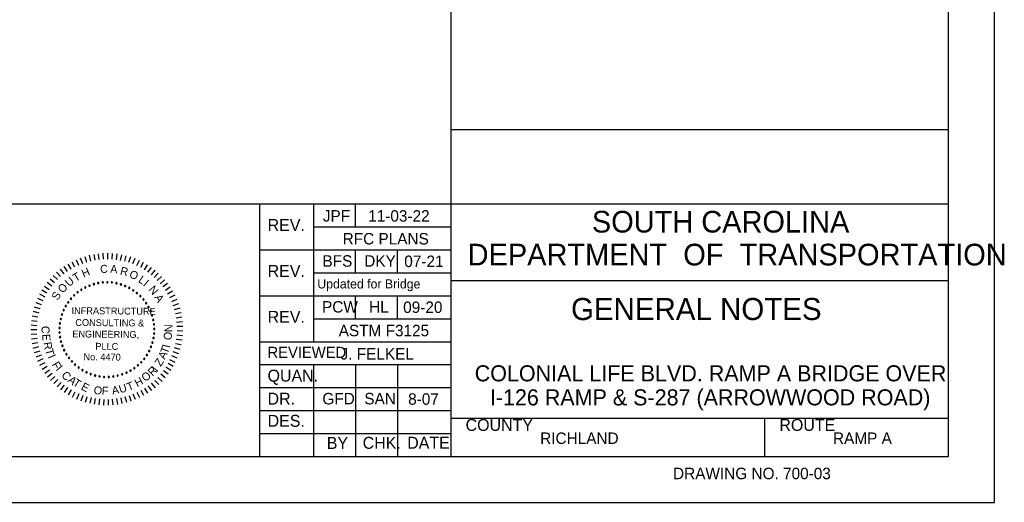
# Model space of a CAD drawing. Extents: x -1.3 to 34.8, y 0.8 to 22.8.
# Drawn here: x 24.06 to 34.78, y 0.82 to 6.08 of the extents above; entities that cross this region are included whole.
import ezdxf

# ---------------------------------------------------------------- set-up
doc = ezdxf.new("R2010")
doc.units = 0
for name, color, linetype in [('BR_BORDER LINES', 7, 'Continuous'), ('BR_TEXT', 7, 'Continuous'), ('Level 31', 7, 'Continuous')]:
    doc.layers.add(name, color=color, linetype=linetype)

msp = doc.modelspace()

# ---------------------------------------------------------------- linework, layer by layer
at = {"layer": 'BR_BORDER LINES'}
for p, q in [((34.177, 1.318), (34.177, 22.318)), ((28.76, 1.318), (28.76, 6.595)), ((28.76, 4.88), (34.177, 4.88)), ((21.311, 4.068), (26.676, 4.068)), ((26.676, 1.318), (26.676, 4.068)), ((26.676, 4.068), (34.177, 4.068)), ((27.26, 4.068), (27.26, 2.568)), ((27.718, 3.818), (27.718, 4.068)), ((27.26, 3.818), (28.76, 3.818)), ((26.676, 3.568), (28.76, 3.568)), ((27.718, 3.318), (27.718, 3.568)), ((28.176, 3.318), (28.176, 3.568)), ((27.26, 3.318), (28.76, 3.318)), ((28.76, 3.235), (28.76, 3.235)), ((28.76, 3.235), (34.177, 3.235)), ((26.676, 3.068), (28.76, 3.068)), ((27.718, 2.818), (27.718, 3.068)), ((28.176, 2.818), (28.176, 3.068)), ((27.26, 2.818), (28.76, 2.818)), ((26.676, 2.568), (28.76, 2.568)), ((26.676, 2.318), (28.76, 2.318)), ((27.26, 2.318), (27.26, 1.318)), ((27.718, 2.318), (27.718, 1.318)), ((28.176, 2.318), (28.176, 1.318)), ((26.676, 2.068), (28.76, 2.068)), ((26.676, 1.818), (28.76, 1.818)), ((28.76, 1.735), (34.177, 1.735)), ((28.857, 1.735), (34.177, 1.735)), ((32.177, 1.318), (32.177, 1.735)), ((26.676, 1.568), (28.76, 1.568)), ((0.511, 1.318), (34.177, 1.318))]:
    msp.add_line(p, q, dxfattribs=at)
at = {"layer": 'BR_TEXT'}
for p, q in [((24.629, 3.439), (24.658, 3.382)), ((24.674, 3.461), (24.7, 3.402)), ((24.721, 3.48), (24.743, 3.42)), ((24.769, 3.496), (24.788, 3.435)), ((24.818, 3.509), (24.832, 3.447)), ((24.867, 3.519), (24.878, 3.456)), ((24.917, 3.526), (24.924, 3.463)), ((24.967, 3.531), (24.971, 3.467)), ((25.018, 3.532), (25.017, 3.468)), ((25.068, 3.53), (25.064, 3.466)), ((25.118, 3.524), (25.11, 3.461)), ((25.168, 3.516), (25.156, 3.454)), ((25.218, 3.505), (25.202, 3.444)), ((25.266, 3.491), (25.246, 3.43)), ((25.313, 3.474), (25.29, 3.415)), ((25.36, 3.454), (25.333, 3.396)), ((24.463, 3.325), (24.505, 3.277)), ((24.501, 3.357), (24.541, 3.307)), ((24.542, 3.387), (24.578, 3.334)), ((24.585, 3.414), (24.618, 3.359)), ((25.405, 3.431), (25.375, 3.375)), ((25.449, 3.406), (25.415, 3.352)), ((25.491, 3.378), (25.454, 3.326)), ((25.531, 3.347), (25.491, 3.298)), ((24.391, 3.254), (24.439, 3.211)), ((24.426, 3.29), (24.471, 3.245)), ((25.569, 3.314), (25.526, 3.267)), ((25.605, 3.279), (25.559, 3.235)), ((25.639, 3.242), (25.591, 3.2)), ((24.301, 3.132), (24.356, 3.099)), ((24.329, 3.174), (24.381, 3.138)), ((24.359, 3.215), (24.409, 3.176)), ((25.671, 3.202), (25.62, 3.164)), ((25.7, 3.161), (25.647, 3.126)), ((25.726, 3.118), (25.671, 3.086)), ((24.255, 3.042), (24.313, 3.016)), ((24.277, 3.088), (24.333, 3.058)), ((25.75, 3.074), (25.693, 3.045)), ((25.772, 3.028), (25.713, 3.003)), ((24.206, 2.899), (24.268, 2.884)), ((24.219, 2.948), (24.28, 2.929)), ((24.235, 2.996), (24.295, 2.973)), ((25.79, 2.981), (25.73, 2.96)), ((25.805, 2.933), (25.744, 2.915)), ((24.188, 2.8), (24.251, 2.793)), ((24.195, 2.85), (24.258, 2.839)), ((25.818, 2.884), (25.756, 2.87)), ((25.827, 2.834), (25.764, 2.824)), ((24.182, 2.699), (24.246, 2.7)), ((24.184, 2.75), (24.247, 2.746)), ((25.834, 2.784), (25.77, 2.778)), ((25.837, 2.734), (25.773, 2.732)), ((25.837, 2.683), (25.774, 2.685)), ((24.184, 2.649), (24.248, 2.653)), ((24.189, 2.598), (24.252, 2.607)), ((25.829, 2.583), (25.766, 2.592)), ((25.835, 2.633), (25.771, 2.638)), ((24.197, 2.549), (24.259, 2.561)), ((24.208, 2.499), (24.27, 2.515)), ((24.222, 2.451), (24.282, 2.47)), ((25.808, 2.484), (25.747, 2.501)), ((25.82, 2.533), (25.758, 2.546)), ((24.239, 2.403), (24.298, 2.426)), ((24.259, 2.357), (24.316, 2.384)), ((25.755, 2.343), (25.697, 2.37)), ((25.775, 2.389), (25.716, 2.413)), ((25.793, 2.436), (25.733, 2.456)), ((24.281, 2.312), (24.337, 2.342)), ((24.306, 2.268), (24.36, 2.302)), ((24.334, 2.226), (24.386, 2.263)), ((25.705, 2.255), (25.652, 2.289)), ((25.731, 2.298), (25.676, 2.329)), ((24.365, 2.186), (24.414, 2.225)), ((24.397, 2.147), (24.445, 2.19)), ((24.433, 2.111), (24.477, 2.157)), ((25.576, 2.1), (25.532, 2.146)), ((25.612, 2.136), (25.565, 2.179)), ((25.645, 2.173), (25.596, 2.214)), ((25.676, 2.213), (25.625, 2.251)), ((24.47, 2.077), (24.511, 2.125)), ((24.509, 2.045), (24.548, 2.096)), ((24.55, 2.016), (24.585, 2.069)), ((24.593, 1.989), (24.625, 2.044)), ((25.457, 2.007), (25.422, 2.061)), ((25.498, 2.036), (25.461, 2.087)), ((25.538, 2.067), (25.497, 2.116)), ((24.637, 1.965), (24.666, 2.022)), ((24.683, 1.943), (24.708, 2.002)), ((24.73, 1.925), (24.751, 1.985)), ((24.778, 1.909), (24.796, 1.971)), ((24.827, 1.897), (24.841, 1.959)), ((24.876, 1.887), (24.887, 1.95)), ((24.927, 1.88), (24.933, 1.944)), ((24.977, 1.877), (24.979, 1.94)), ((25.027, 1.876), (25.026, 1.94)), ((25.078, 1.879), (25.072, 1.942)), ((25.128, 1.885), (25.119, 1.948)), ((25.178, 1.893), (25.165, 1.956)), ((25.227, 1.905), (25.21, 1.967)), ((25.275, 1.92), (25.255, 1.98)), ((25.322, 1.937), (25.298, 1.996)), ((25.369, 1.958), (25.341, 2.015)), ((25.413, 1.981), (25.382, 2.037))]:
    msp.add_line(p, q, dxfattribs=at)
for centre, start, end in [((24.966, 3.214), 5.0653, 185.0653), ((25.015, 3.215), 359.5268, 179.5268), ((25.065, 3.213), 353.9884, 173.9884), ((24.691, 3.105), 38.2961, 218.2961), ((24.732, 3.134), 32.7576, 212.7576), ((24.732, 3.134), 212.7576, 32.7576), ((24.775, 3.159), 27.2191, 207.2191), ((24.775, 3.159), 207.2191, 27.2191), ((24.821, 3.179), 21.6807, 201.6807), ((24.821, 3.179), 201.6807, 21.6807), ((24.868, 3.195), 16.1422, 196.1422), ((24.868, 3.195), 196.1422, 16.1422), ((24.916, 3.207), 10.6038, 190.6038), ((24.916, 3.207), 190.6038, 10.6038), ((24.966, 3.214), 185.0653, 5.0653), ((25.015, 3.215), 179.5268, 359.5268), ((25.065, 3.213), 173.9884, 353.9884), ((25.114, 3.205), 348.4499, 168.4499), ((25.114, 3.205), 168.4499, 348.4499), ((25.163, 3.192), 342.9114, 162.9114), ((25.163, 3.192), 162.9114, 342.9114), ((25.209, 3.175), 157.373, 337.373), ((25.209, 3.175), 337.373, 157.373), ((25.254, 3.154), 151.8345, 331.8345), ((25.254, 3.154), 331.8345, 151.8345), ((25.297, 3.128), 146.2961, 326.2961), ((25.297, 3.128), 326.2961, 146.2961), ((24.589, 2.997), 54.9114, 234.9114), ((24.589, 2.997), 234.9114, 54.9114), ((24.619, 3.036), 49.373, 229.373), ((24.619, 3.036), 229.373, 49.373), ((24.654, 3.072), 43.8345, 223.8345), ((24.654, 3.072), 223.8345, 43.8345), ((24.691, 3.105), 218.2961, 38.2961), ((25.337, 3.099), 140.7576, 320.7576), ((25.337, 3.099), 320.7576, 140.7576), ((25.374, 3.065), 135.2191, 315.2191), ((25.374, 3.065), 315.2191, 135.2191), ((25.408, 3.028), 129.6807, 309.6807), ((25.408, 3.028), 309.6807, 129.6807), ((24.539, 2.911), 65.9884, 245.9884), ((24.539, 2.911), 245.9884, 65.9884), ((24.562, 2.955), 60.4499, 240.4499), ((24.562, 2.955), 240.4499, 60.4499), ((25.437, 2.988), 124.1422, 304.1422), ((25.437, 2.988), 304.1422, 124.1422), ((25.463, 2.946), 118.6038, 298.6038), ((25.463, 2.946), 298.6038, 118.6038), ((25.485, 2.901), 113.0653, 293.0653), ((25.485, 2.901), 293.0653, 113.0653), ((24.508, 2.816), 77.0653, 257.0653), ((24.508, 2.816), 257.0653, 77.0653), ((24.521, 2.864), 71.5268, 251.5268), ((24.521, 2.864), 251.5268, 71.5268), ((25.502, 2.854), 107.5268, 287.5268), ((25.502, 2.854), 287.5268, 107.5268), ((25.515, 2.806), 101.9884, 281.9884), ((25.515, 2.806), 281.9884, 101.9884), ((24.495, 2.718), 88.1422, 268.1422), ((24.499, 2.767), 82.6038, 262.6038), ((24.495, 2.718), 268.1422, 88.1422), ((24.499, 2.767), 262.6038, 82.6038), ((25.523, 2.757), 96.4499, 276.4499), ((25.526, 2.707), 90.9114, 270.9114), ((25.523, 2.757), 276.4499, 96.4499), ((25.526, 2.707), 270.9114, 90.9114), ((24.495, 2.668), 93.6807, 273.6807), ((24.501, 2.618), 99.2191, 279.2191), ((24.495, 2.668), 273.6807, 93.6807), ((24.501, 2.618), 279.2191, 99.2191), ((24.511, 2.569), 104.7576, 284.7576), ((24.511, 2.569), 284.7576, 104.7576), ((25.518, 2.608), 79.8345, 259.8345), ((25.518, 2.608), 259.8345, 79.8345), ((25.524, 2.657), 85.373, 265.373), ((25.524, 2.657), 265.373, 85.373), ((24.526, 2.522), 110.2961, 290.2961), ((24.526, 2.522), 290.2961, 110.2961), ((24.545, 2.476), 115.8345, 295.8345), ((24.545, 2.476), 295.8345, 115.8345), ((25.47, 2.466), 63.2191, 243.2191), ((25.47, 2.466), 243.2191, 63.2191), ((25.49, 2.512), 68.7576, 248.7576), ((25.49, 2.512), 248.7576, 68.7576), ((25.506, 2.559), 74.2961, 254.2961), ((25.506, 2.559), 254.2961, 74.2961), ((24.569, 2.432), 121.373, 301.373), ((24.569, 2.432), 301.373, 121.373), ((24.597, 2.391), 126.9114, 306.9114), ((24.597, 2.391), 306.9114, 126.9114), ((24.629, 2.352), 312.4499, 132.4499), ((25.417, 2.382), 52.1422, 232.1422), ((25.417, 2.382), 232.1422, 52.1422), ((25.445, 2.423), 57.6807, 237.6807), ((25.445, 2.423), 237.6807, 57.6807), ((24.629, 2.352), 132.4499, 312.4499), ((24.664, 2.317), 137.9884, 317.9884), ((24.664, 2.317), 317.9884, 137.9884), ((24.703, 2.286), 143.5268, 323.5268), ((24.703, 2.286), 323.5268, 143.5268), ((24.744, 2.258), 149.0653, 329.0653), ((24.744, 2.258), 329.0653, 149.0653), ((25.267, 2.253), 29.9884, 209.9884), ((25.267, 2.253), 209.9884, 29.9884), ((25.309, 2.279), 35.5268, 215.5268), ((25.309, 2.279), 215.5268, 35.5268), ((25.348, 2.31), 41.0653, 221.0653), ((25.348, 2.31), 221.0653, 41.0653), ((25.384, 2.345), 46.6038, 226.6038), ((25.384, 2.345), 226.6038, 46.6038), ((24.788, 2.234), 154.6038, 334.6038), ((24.788, 2.234), 334.6038, 154.6038), ((24.834, 2.215), 340.1422, 160.1422), ((24.834, 2.215), 160.1422, 340.1422), ((24.882, 2.2), 345.6807, 165.6807), ((24.882, 2.2), 165.6807, 345.6807), ((24.93, 2.19), 351.2191, 171.2191), ((24.93, 2.19), 171.2191, 351.2191), ((24.98, 2.185), 356.7576, 176.7576), ((24.98, 2.185), 176.7576, 356.7576), ((25.03, 2.184), 2.2961, 182.2961), ((25.03, 2.184), 182.2961, 2.2961), ((25.079, 2.189), 7.8345, 187.8345), ((25.079, 2.189), 187.8345, 7.8345), ((25.128, 2.198), 13.373, 193.373), ((25.128, 2.198), 193.373, 13.373), ((25.176, 2.212), 18.9114, 198.9114), ((25.176, 2.212), 198.9114, 18.9114), ((25.223, 2.23), 24.4499, 204.4499), ((25.223, 2.23), 204.4499, 24.4499)]:
    msp.add_arc(centre, 0.00701, start, end, dxfattribs=at)
at = {"layer": 'Level 31'}
msp.add_line((31.468, 2.795), (31.468, 2.795), dxfattribs=at)
msp.add_lwpolyline([(-1.323, 22.818), (-1.323, 0.818), (34.677, 0.818), (34.677, 22.818)], dxfattribs=at)

# ---------------------------------------------------------------- texts
at = {"layer": 'BR_TEXT'}
for s, height, p in [('JPF', 0.125, (27.362, 3.876)), ('11-03-22', 0.125, (27.856, 3.876)), ('SOUTH CAROLINA', 0.23587, (30.292, 3.757)), ('REV.', 0.13, (26.761, 3.774)), ('RFC PLANS', 0.125, (27.578, 3.627)), ('DEPARTMENT  OF  TRANSPORTATION', 0.23587, (28.939, 3.399)), ('BFS', 0.125, (27.358, 3.385)), ('DKY', 0.125, (27.813, 3.385)), ('07-21', 0.125, (28.249, 3.381)), ('REV.', 0.13, (26.761, 3.274)), ('Updated for Bridge', 0.1, (27.302, 3.148)), ('PCW', 0.125, (27.353, 2.885)), ('HL', 0.125, (27.866, 2.885)), ('09-20', 0.125, (28.237, 2.881)), ('GENERAL NOTES', 0.24, (30.065, 2.804)), ('REV.', 0.13, (26.761, 2.774)), ('ASTM F3125', 0.125, (27.535, 2.627)), ('REVIEWED', 0.12, (26.76, 2.392)), ('J. FELKEL', 0.125, (27.555, 2.373)), ('QUAN.', 0.13, (26.76, 2.133)), ('COLONIAL LIFE BLVD. RAMP A BRIDGE OVER', 0.175, (29.016, 2.136)), ('I-126 RAMP & S-287 (ARROWWOOD ROAD)', 0.175, (29.181, 1.874)), ('DR.', 0.13, (26.76, 1.882)), ('GFD', 0.125, (27.357, 1.885)), ('SAN', 0.125, (27.814, 1.885)), ('8-07', 0.125, (28.291, 1.881)), ('DES.', 0.13, (26.761, 1.641)), ('COUNTY', 0.13, (28.917, 1.596)), ('ROUTE', 0.13, (32.334, 1.596)), ('BY', 0.13, (27.405, 1.4)), ('CHK.', 0.13, (27.796, 1.401)), ('DATE', 0.13, (28.281, 1.402)), ('RICHLAND', 0.125, (29.729, 1.454)), ('RAMP A', 0.125, (32.918, 1.454)), ('DRAWING NO. 700-03', 0.125, (31.176, 1.07))]:
    msp.add_text(s, height=height, dxfattribs=at).set_placement(p)
for s, height, rotation, p in [('T', 0.0872, 31.8182, (24.672, 3.217)), ('H', 0.0872, 22.7882, (24.757, 3.265)), ('C', 0.0872, 4.7281, (24.94, 3.314)), ('A', 0.0872, 355.6981, (25.044, 3.319)), ('R', 0.0872, 346.6681, (25.149, 3.302)), ('O', 0.0872, 337.638, (25.246, 3.272)), ('U', 0.0872, 40.8482, (24.599, 3.161)), ('L', 0.0872, 327.108, (25.345, 3.222)), ('I', 0.0872, 319.578, (25.398, 3.184)), ('S', 0.0872, 58.9083, (24.476, 3.012)), ('O', 0.0872, 49.8782, (24.532, 3.09)), ('N', 0.0872, 310.548, (25.459, 3.133)), ('A', 0.0872, 301.5179, (25.524, 3.051)), ('INFRASTRUCTURE', 0.07477, 359.5268, (24.625, 2.869)), ('CONSULTING &', 0.07477, 359.5268, (24.666, 2.74)), ('C', 0.0872, 267.025, (24.301, 2.742)), ('ENGINEERING,', 0.07477, 359.5268, (24.633, 2.615)), ('N', 0.0872, 89.2085, (25.723, 2.672)), ('E', 0.0872, 273.025, (24.306, 2.65)), ('O', 0.0872, 83.2085, (25.712, 2.581)), ('R', 0.0872, 279.025, (24.319, 2.558)), ('T', 0.0872, 285.025, (24.336, 2.479)), ('PLLC', 0.0748, 359.5268, (24.884, 2.481)), ('T', 0.0872, 69.3954, (25.671, 2.429)), ('I', 0.0872, 77.9093, (25.696, 2.496)), ('I', 0.0872, 293.7713, (24.366, 2.406)), ('No. 4470', 0.0748, 359.5268, (24.755, 2.365)), ('Z', 0.0872, 57.3954, (25.596, 2.292)), ('A', 0.0872, 63.3954, (25.64, 2.368)), ('F', 0.0872, 299.7713, (24.407, 2.32)), ('I', 0.0872, 308.5268, (24.449, 2.266)), ('R', 0.0872, 44.5268, (25.506, 2.187)), ('I', 0.0872, 52.3339, (25.555, 2.234)), ('C', 0.0872, 314.5268, (24.508, 2.196)), ('A', 0.0872, 320.5268, (24.578, 2.137)), ('T', 0.0872, 326.5268, (24.632, 2.099)), ('H', 0.0872, 28.5268, (25.341, 2.071)), ('O', 0.0872, 38.5268, (25.429, 2.127)), ('E', 0.0872, 332.5268, (24.721, 2.051)), ('O', 0.0872, 350.5268, (24.861, 2.002)), ('F', 0.0872, 356.5268, (24.952, 1.993)), ('A', 0.0872, 10.5268, (25.072, 1.991)), ('U', 0.0872, 16.5268, (25.156, 2.005)), ('T', 0.0872, 22.5268, (25.248, 2.029))]:
    msp.add_text(s, height=height, rotation=rotation, dxfattribs=at).set_placement(p)

doc.saveas('drawing.dxf')
